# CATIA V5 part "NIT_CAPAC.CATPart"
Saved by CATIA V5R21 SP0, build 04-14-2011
Part number: NIT CAPAC RULMENTI
Publications: "Mating Face", "Axis"
Bounding box of the stored display mesh (mm): x -23.5 to 3.5, y -4 to 4, z -4.619 to 4.619
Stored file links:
  C:\Users\MIRCEA\Desktop\MOM\Mogan\model\NIT_CAPAC.CATPart
  C:\Program Files (x86)\Dassault Systemes\B21\intel_a\startup\components\MechanicalStandardParts\EN_Standards\Design_Tables\EN_ISO_4014_GRADES_A_B_HEXAGON_HEAD_BOLT.txt
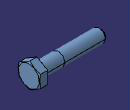
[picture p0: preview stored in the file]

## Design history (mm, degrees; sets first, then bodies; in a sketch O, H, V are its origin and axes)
Parameters
  d_dia = 5 mm
  l_length = 23.5 mm
  s_nom_across_flats = 8 mm
  k_max_head_depth = 3.5 mm
  dw_min = 7 mm
  r_min = 0.2 mm
  c_max = 0.5 mm
  p_pitch = 0.8 mm
  threading = 16 mm
Set1
  DatumSurface1
Body1 "PartBody" (main body)
  Sketch1 on yz-plane, origin (0, 0, 0), H (0, 1, 0), V (0, 0, 1)
    circle A1 centre (0, 0) radius 3.5
    radius A1 = 3.5 {= dw_min /2}
  Pad1: profile Sketch1, direction (1, 0, 0), length 0.5 {= c_max}
  Sketch2 on face of Pad1, origin (0.5, 0, 0), H (0, 1, 0), V (0, 0, 1)
    point P1 (4, -2.3094)
    point P2 (4, 2.3094)
    point P3 (0, 4.6188)
    point P4 (-4, 2.3094)
    point P5 (-4, -2.3094)
    point P6 (0, -4.6188)
    point P7 (4, 0)
    line L1 (4, -2.3094) -> (4, 2.3094)
    line L2 (4, 2.3094) -> (0, 4.6188)
    line L3 (0, 4.6188) -> (-4, 2.3094)
    line L4 (-4, 2.3094) -> (-4, -2.3094)
    line L5 (-4, -2.3094) -> (0, -4.6188)
    line L6 (0, -4.6188) -> (4, -2.3094)
    construction line L7 (0, 0) -> (4, 0)
    construction circle A1 centre (0, 0) radius 4.6188
    construction arc A2 centre (-4, -2.3094) radius 4.6188 from (-4, 2.3094) to (0, -4.6188) cw
    construction arc A3 centre (4, 2.3094) radius 4.6188 from (0, 4.6188) to (4, -2.3094) ccw
    point P8 (-4, -2.3094)
    point P9 (4, 2.3094)
    distance L1 L4 = 8 {= s_nom_across_flats}
    horizontal: L7 H
    coincidence: A1 P1, A1 P2, A1 P3, A1 P4, A1 P5, A1 P6, A2 P4, A2 P6, A2 O, P8 P5, A3 P3, A3 P1, A3 O, P9 P2
    midpoint: P7 L1
  Pad2: profile Sketch2, direction (1, 0, 0), length 3 {= k_max_head_depth -c_max}
  Sketch3 on zx-plane, origin (0, 0, 0), H (-1, 0, 0), V (0, 0, 1)
    point P1 (-3.5, 3.9821)
    axis line L1 (-94.6904, 0) -> (76.7146, 0)
    reference intersected line E1 through (1000000, 0) direction (-1, 0) from xy-plane
    line L2 (-3.1324, 4.6188) -> (-3.5, 3.9821)
    line L3 (-3.1324, 4.6188) -> (-3.5, 4.6188)
    line L4 (-3.5, 4.6188) -> (-3.5, 3.9821)
    reference projected line E2 (-0.8, 4.6188) -> (-18.28, 4.6188) from edge [face of Pad2 | face of Pad2]
    distance P1 H = 3.9821 {= s_nom_across_flats /2.009}
    distance P1 V = 3.5 {= k_max_head_depth}
    angle L4 L2 = 30
    horizontal: L1 H, L3 H
    coincidence: L1 E1, L3 E2
    vertical: L4 V
  Groove1: profile Sketch3, axis Sketch3.L1, angle 360
  Sketch4 on face of Pad1, origin (0, 0, 0), H (0, -1, 0), V (0, 0, 1)
    circle A1 centre (0, 0) radius 2.5
    radius A1 = 2.5 {= d_dia /2}
  Pad3: profile Sketch4, direction (-1, 0, 0), length 7.5 {= l_length -threading}
  Sketch5 on face of Pad3, origin (-7.5, 0, 0), H (0, -1, 0), V (0, 0, 1)
    circle A1 centre (0, 0) radius 2.439
    radius A1 = 2.439 {= d_dia /2.05}
  Pad4: profile Sketch5, direction (-1, 0, 0), length 16 {= threading}
  Chamfer1: length 0.8 {= p_pitch}, angle 45, on face of Pad4
  Fillet1: radius 0.2 {= r_min}, on edge [face of Pad3 | face of Pad1]
  Thread1: diameter 4.878 {= d_dia /1.025}, depth 16 {= threading}, pitch 1, on face of Pad4, from face of Pad4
